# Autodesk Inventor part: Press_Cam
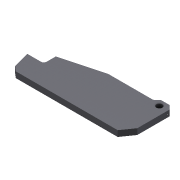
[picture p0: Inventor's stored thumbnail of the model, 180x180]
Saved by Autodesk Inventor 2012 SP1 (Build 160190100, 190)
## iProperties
Created: 2005-12
Part Number: Press_Cam
Document SubType Name: Modeling
Designer: t_munrn
Density: 1 g/cm^3
Material: Default
Author: t_munrn
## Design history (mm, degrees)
sketch "Sketch1"
  geometry: L1 (-17.5, 12.75)-(17.5, 12.75); L2 (17.5, 12.75)-(17.5, -64.4); L3 (-236.5, -44.4)-(-201.5, -44.4); L4 (-201.5, -44.4)-(-201.5, -18.792); L5 (-201.5, -18.792)-(-113.639, 4.75); L6 (-113.639, 4.75)-(-17.5, 4.75); L7 (-17.5, 4.75)-(-17.5, 12.75); L8 (17.5, -64.4)-(0.345, -88.9); L9 (0.345, -88.9)-(-216.5, -88.9); L10 (-216.5, -88.9)-(-226.919, -80.158); L11 (0, 0)-(0, 12.75); L12 (-226.919, -80.158)-(-236.5, -44.4); C1 r 6.375 at (0, 0); 1 further point
  constraints: 24 end point, 4 parallel, 3 perpendicular, 1 centre point, 1 coincident, 1 horizontal, 1 midpoint
  dimensions: "d0" = 12.75 diameter of C1; "d1" = 12.75 distance of L11.start L11.end; "d2" = 35 distance of L1.start L1.end; "d3" = 77.15 distance of L1.end L2.end; "d6" = 35 deg angle of L2 L8; "d9" = 57.15 distance between parallel lines of L3 L1; "d11" = 15 deg angle of L3 L5; "d12" = 34 distance from line of L5 point (0, 0); "d13" = 8 distance of L6.end L1.start; "d34" = 88.9 distance from line of L9 point (0, 0); "d35" = 35 distance from line of L3.start L4; "d36" = 75 deg angle of L12 L3; "d37" = 236.5 horizontal distance of L3.start L11.start; "d38" = 40 deg angle of L9 L10; "d39" = 234 distance from line of L9.end L2
extrude "Extrusion1" new body sketch "Sketch1" stored distance "d14" = 12.5; taper "d15" = 0 deg
chamfer "Chamfer1" distance "d23" = 8; stored, may be unused: second distance "d24" = 2, angle "d25" = 45 deg
sketch "Sketch3"
  geometry: 1 further point
hole "Hole1" sketch "Sketch3" at (6.25, 64.4) diameter "d26" = 2.459; stored, may be unused: countersink angle "d30" = 90 deg, drill point angle "d32" = 118 deg; dims "d27" = 6, "d28" = 4, "d29" = 2, "d31" = 8
fillet "Fillet3" dims "d40" = 6
sketch "Sketch4"
  geometry: L1 (0, -37.019)-(12.5, 0); 1 further point
  constraints: 2 end point, 1 midpoint
hole "Hole2" sketch "Sketch4" at (6.25, -18.509) diameter "d41" = 6.647; stored, may be unused: countersink angle "d45" = 90 deg, drill point angle "d47" = 118 deg; dims "d42" = 20, "d43" = 4, "d44" = 2, "d46" = 25
body "Solid1"
